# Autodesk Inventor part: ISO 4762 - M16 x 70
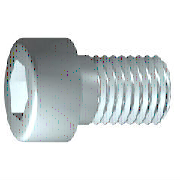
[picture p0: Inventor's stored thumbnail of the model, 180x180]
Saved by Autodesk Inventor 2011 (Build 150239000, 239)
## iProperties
IsCustomPart: 0
Created: 2010-02
Part Number: ISO 4762 - M16 x 70
Material: Stainless Steel, 440C
Description: Hexagon Socket Head Cap Screw
Document SubType Name: Modeling
Standard: ISO 4762
Designer: 129877
Standard Revision: Fourth edition 2004-03-01
Standards Organization: ISO
Language: en-US
Size Designation: M16 x 70
Categories: <MemberInstance><Categories><Category DisplayName="Fasteners" InternalName="e4da775c-781d-43d5-af7c-5136215cf5a6" Mnemonic="FSTN"><Category DisplayName="Bolts"
Density: 7.75 g/cm^3
Mass: 151.653 g
Surface Area: 59.7075 cm^2
Volume: 19.5681 cm^3
Author: 129877
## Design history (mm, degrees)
body "Solid1"
workplane "Work Plane1"
fillet "Fillet2" dims "d30" = 0.1 (= R)
revolve "Body" stored, may be unused: angle "d10" = 90 deg
sketch "Sketch2"
  geometry: L1 (0, -16.8)-(0, 16.8) reference; L2 (-16.8, 0)-(16.8, 0) reference; L3 (8.083, 0)-(4.041, -7); L4 (4.041, -7)-(-4.041, -7); L5 (-4.041, -7)-(-8.083, 0); L6 (-8.083, 0)-(-4.041, 7); L7 (-4.041, 7)-(4.041, 7); L8 (4.041, 7)-(8.083, 0); 2 further points
  constraints: 12 end point, 1 coincident, 1 horizontal alignment, 1 point on line, 12 other
extrude "Slot" join sketch "Sketch2" stored distance "d11" = 10; taper "d12" = 0 deg
fillet "Fillet1" dims "d17" = 1.6 (= RR)
feature "Thread" dims "d13" = 44 (= GEL), "d14" = 0
chamfer "Chamfer1" distance "d15" = 1.2269 (= -0.5 x SPD + 0.5 x GD); stored, may be unused: second distance "d16" = 1.2269 (= GUL), angle "d27" = 45 deg
sketch "Sketch1"
  geometry: L1 (-3.333, 0)-(70, 0); L2 (70, 0)-(70, 8); L3 (70, 8)-(26, 8); L4 (26, 8)-(24.773, 8); L5 (24.773, 8)-(0, 8); L6 (0, 8)-(0, 12); L7 (0, 12)-(-16, 12); L8 (-16, 12)-(-16, 8.083); L9 (-16, 8.083)-(-8, 8.083); L10 (-8, 8.083)-(-3.333, 0); L11 (-33.2, 0)-(87.2, 0) reference; L12 (0, -2.4)-(0, 14.4) reference; L13 (26, 8)-(0, 8)
  constraints: 22 end point, 6 parallel, 2 collinear, 2 perpendicular, 1 horizontal, 1 point on line
  dimensions: "d1" = 44 distance from line of L3.end L2 (= GEL); "d2" = 1.227 distance of L4.end L3.end (computed from GAL); "d3" = 16 distance between parallel lines of L8 L6 (= KOH); "d4" = 8 distance of L8.end L9.end (= INTI); "d5" = 60 deg angle of L10 L1; "d6" = 16 diameter of L3 L1 (= GD); "d7" = 16 diameter of L5 L1 (= BDM); "d8" = 16.16581 diameter of L9 L1 (= 1.1547 x SW); "d9" = 24 diameter of L7 L1 (= KOD); "d26" = 70 distance between parallel lines of L12 L2 (= NLG)
other parameters: "GD" = 16 [user parameter; used in 2 equation terms], "NLG" = 70 [user parameter; used in 1 equation term], "GEL" = 44 [user parameter; used in 2 equation terms], "KOD" = 24 [user parameter; used in 1 equation term], "KOH" = 16 [user parameter; used in 1 equation term], "INTI" = 8 [user parameter; used in 1 equation term], "GAL" = 1.2269 (= 0.61345 x PTC) [user parameter; used in 1 equation term], "GUL" = 1.2269 (= 0.61345 x PTC) [user parameter; used in 1 equation term], "BDM" = 16 (= NND) [user parameter; used in 1 equation term], "SW" = 14 [user parameter; used in 2 equation terms], "RR" = 1.6 [user parameter; used in 1 equation term], "SPD" = 13.5462 (= NND - 1.2269 x PTC) [user parameter; used in 1 equation term], "d19" = 0, "d28" = 0, "d29" = 0, "R" = 0.1 [user parameter; used in 1 equation term], "TOA" = 30 deg [user parameter], "GD1" = 13.5462 (= THREADDIA - 1.2269 x PTC) [user parameter], "THREADDIA" = 16 [user parameter; used in 1 equation term], "FAWI" = 45 deg [user parameter], "TPU" = 5 (computed from PTC) [user parameter], "PTC" = 2 [user parameter; used in 5 equation terms], "NND" = 16 [user parameter; used in 2 equation terms], "E0" = 16.17 (= 1.155 x SW) [user parameter]
